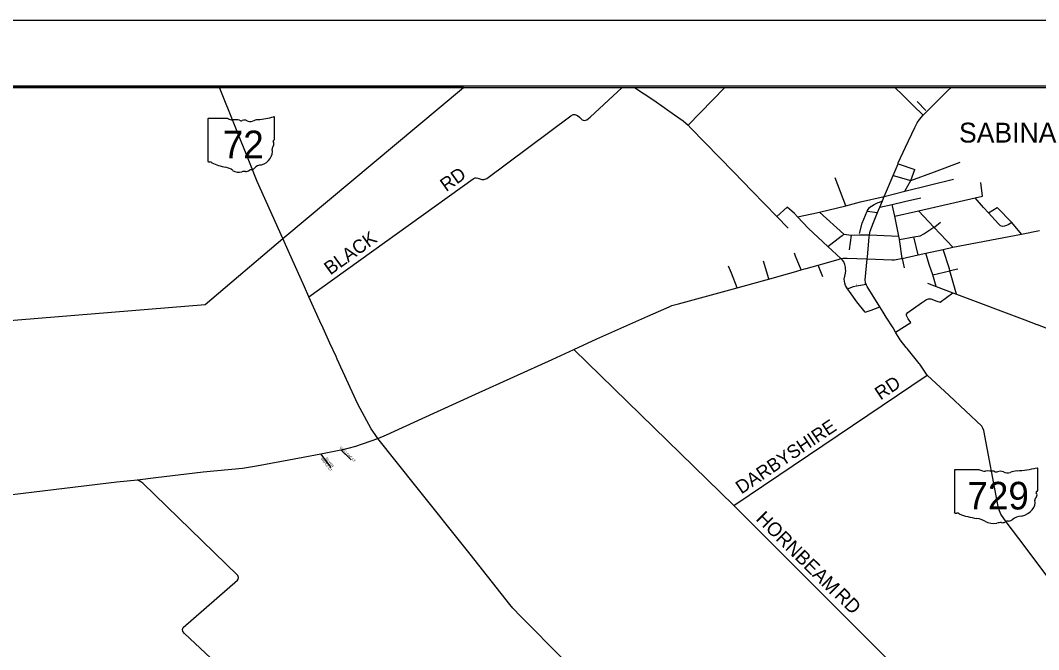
# Model space of a CAD drawing. Extents: x 0 to 784, y 0 to 440.
# Drawn here: x 111 to 266.5, y 343.9 to 440 of the extents above; entities that cross this region are included whole.
import ezdxf

# ---------------------------------------------------------------- set-up
doc = ezdxf.new("R2010")
doc.units = 0
for name, color, linetype in [('Default', 7, 'Continuous'), ('SH_Border', 7, 'Continuous'), ('SH_Cut_Line', 7, 'Continuous')]:
    doc.layers.add(name, color=color, linetype=linetype)

msp = doc.modelspace()

# ---------------------------------------------------------------- linework, layer by layer
at = {"layer": 'Default'}
for p, q in [((178.64, 429.76), (30.04, 429.76)), ((139.59, 424.91), (139.59, 418.5)), ((142.68, 425.02), (139.7, 425.02)), ((149.78, 421.83), (149.78, 425.18)), ((149.78, 421.83), (149.78, 421.83)), ((225.28, 400.54), (224.47, 403.23)), ((253.62, 371.3), (253.62, 364.89)), ((257.47, 371.41), (253.74, 371.41)), ((266.35, 368.22), (266.35, 371.57)), ((266.35, 368.22), (266.35, 368.22))]:
    msp.add_line(p, q, dxfattribs=at)
for points in [[(30.04, 417.42), (46.56, 400.57), (46.68, 400.45), (57.02, 389.91), (139.18, 396.63), (151.04, 406.68), (178.64, 429.76)], [(30.04, 429.76), (356.24, 429.76)], [(30.04, 429.76), (356.24, 429.76)], [(30.04, 429.76), (356.24, 429.76)], [(154.37, 399.31), (151.85, 404.86), (151.04, 406.68), (147.16, 415.39), (146.07, 418.12), (141.38, 429.76)], [(155.05, 397.8), (180.15, 415.83), (180.41, 415.96), (180.59, 415.99), (180.86, 415.92), (181.47, 415.71), (181.73, 415.7), (182.2, 415.87), (195.03, 425.41), (195.38, 425.64), (195.63, 425.65), (196.08, 425.49), (196.38, 425.24), (196.6, 424.97), (196.77, 424.81), (197.07, 424.74), (197.47, 424.81), (198.01, 425.2), (202.88, 429.76)], [(204.79, 429.76), (207.71, 427.84), (210.9, 425.56), (212.18, 424.68), (212.95, 423.99), (213.37, 423.53), (219.88, 416.89), (222.76, 413.93)], [(212.95, 423.99), (218.56, 429.76)], [(244.51, 429.76), (245.73, 428.57)], [(251.09, 427.76), (251.09, 427.76), (252.59, 429.24), (253.13, 429.76)], [(245.73, 428.57), (247.35, 427), (248.85, 425.54)], [(248.85, 425.54), (248.85, 425.54), (251.09, 427.76)], [(249.27, 426.26), (247.93, 427.62)], [(243.24, 413.92), (243.24, 413.92), (244.26, 416.34), (245.01, 418.12), (245.06, 418.24), (246.13, 420.64), (247.59, 423.64), (247.94, 424.35), (248.28, 424.86), (248.85, 425.54)], [(245.01, 418.12), (247.6, 417.25)], [(246.07, 413.93), (246.97, 415.56), (247.6, 417.25)], [(246.97, 415.56), (250.56, 416.89), (254.52, 418.34)], [(237.06, 411.7), (235.41, 415.98)], [(242.91, 413.12), (246.07, 413.93), (253.49, 415.74)], [(244.26, 416.34), (246.97, 415.56)], [(222.76, 413.93), (222.76, 413.92), (226.5, 410.07), (228.26, 408.27)], [(240.33, 403.92), (240.33, 403.92), (240.62, 406.89), (240.66, 407.19), (240.67, 407.28), (240.77, 407.82), (241.26, 409.17), (241.89, 410.68), (242.22, 411.47), (242.63, 412.44), (242.91, 413.12), (243.24, 413.92)], [(257.89, 413.17), (257.67, 415.23)], [(229.67, 410.01), (231.83, 410.48), (233, 410.72), (237.06, 411.7), (239.3, 412.29), (242.91, 413.12)], [(240.95, 411.66), (241.35, 411.9), (241.96, 412.18), (242.2, 412.27), (242.63, 412.44)], [(242.22, 411.47), (244.13, 411.91), (245.99, 412.34), (245.99, 412.34)], [(244.52, 410.1), (248.13, 410.93), (256.79, 412.92), (257.89, 413.17)], [(245.99, 412.34), (248.51, 412.93)], [(262.37, 409.13), (261.84, 408.81), (261.58, 408.7), (261.29, 408.6), (261.03, 408.55), (260.64, 408.62), (260.34, 408.93), (258.81, 410.64), (258.07, 411.46), (256.79, 412.92)], [(226.5, 410.07), (228.09, 411.47)], [(236.26, 403.64), (234.27, 405.49), (231.36, 408.25), (229.67, 410.01), (229.2, 410.5), (228.09, 411.47)], [(236.74, 407.39), (233, 410.72)], [(239.14, 407.49), (239.56, 409.03), (240.07, 410.29), (240.28, 410.86), (240.61, 411.38), (240.92, 411.64), (240.95, 411.66), (240.95, 411.66)], [(240.28, 410.86), (241.89, 410.68)], [(245.65, 403.67), (245.23, 406.55), (245.23, 406.58), (245.12, 407.08), (245.02, 407.58), (244.52, 410.1), (244.13, 411.91)], [(253.38, 405.36), (250.49, 408.42), (248.13, 410.93)], [(258.81, 410.64), (258.81, 410.64), (260.13, 411.46)], [(263.85, 407.39), (262.37, 409.13), (260.13, 411.46)], [(245.23, 406.55), (247.44, 406.94), (248.37, 407.09), (248.97, 407.44), (250.49, 408.42), (250.62, 408.51), (251.51, 409.2)], [(253.38, 405.36), (263.85, 407.39), (266.62, 407.92), (266.62, 407.92)], [(234.27, 405.49), (236.33, 407.04), (236.57, 407.23), (236.74, 407.39), (237.9, 407.23), (239.1, 407.25), (239.13, 407.25)], [(237.61, 404.98), (237.9, 407.23)], [(239.13, 407.25), (239.14, 407.25), (240.67, 407.28)], [(240.67, 407.28), (240.67, 407.28), (245.12, 407.08)], [(248.1, 404.2), (247.44, 406.94)], [(230.24, 401.9), (229.36, 404.03), (229.19, 404.48)], [(230.95, 402.1), (230.96, 402.11), (232.81, 402.64), (233.53, 402.84), (235.87, 403.52), (236.26, 403.64), (236.65, 403.72), (237.25, 403.71), (238.72, 403.66), (240.3, 403.6), (244.05, 403.45), (244.5, 403.46), (245.49, 403.64), (245.65, 403.67), (248.1, 404.2), (249.26, 404.46), (251.89, 405.03), (253.38, 405.36)], [(250.85, 399.39), (250.34, 401.15), (249.78, 402.76), (249.26, 404.46)], [(253.96, 398.22), (252.94, 401.79), (252.86, 402.06), (251.89, 405.03)], [(240.01, 395.45), (238.72, 397.06), (237.6, 398.62), (237.31, 399.01), (237, 399.54), (236.89, 399.89), (236.8, 400.49), (236.99, 401.39), (237.02, 401.83), (237.01, 402.01), (236.97, 402.31), (236.91, 402.74), (236.76, 403.14), (236.55, 403.39), (236.26, 403.64)], [(240.07, 399.91), (240.04, 399.99), (239.99, 400.42), (240.3, 403.6), (240.33, 403.92)], [(245.65, 403.67), (245.93, 402.24)], [(220.46, 399.19), (219.57, 401.4), (219.12, 402.49)], [(224.31, 400.25), (224.32, 400.25), (225.41, 400.55), (228.11, 401.29), (229.06, 401.56), (230.24, 401.9), (230.95, 402.1)], [(233.55, 400.87), (232.81, 402.64)], [(250.34, 401.15), (252.94, 401.79), (253, 401.8), (253, 401.8)], [(253, 401.8), (254.14, 402.08)], [(109.7, 367.64), (125.69, 369.54), (128.88, 369.87), (131.68, 370.22), (138.87, 371.09), (144.9, 371.67), (147.03, 372.02), (154.14, 373.35), (156.88, 373.86), (159.9, 374.42), (160.08, 374.46), (161.02, 374.69), (162.23, 375), (165.56, 376.17), (166.89, 376.71), (172.36, 379.21), (180.5, 382.96), (192.21, 388.23), (195.52, 389.76), (199.02, 391.4), (206.82, 394.86), (210.04, 396.28), (210.47, 396.46), (211.49, 396.72), (220.46, 399.19), (224.31, 400.25)], [(237.31, 399.01), (238.2, 399.37), (238.65, 399.5), (239.26, 399.6), (240.14, 399.72)], [(246.39, 389.92), (246.28, 390.05), (245.32, 391.23), (244.64, 392.39), (244.26, 393.05), (243.21, 394.71), (242.74, 395.44), (242.23, 396.26), (240.28, 399.38), (240.2, 399.58), (240.14, 399.72), (240.07, 399.91)], [(249.51, 399.9), (250.85, 399.39), (253.4, 398.43), (253.96, 398.22), (264.37, 394.31), (266.23, 393.59), (266.24, 393.59)], [(164.8, 377.29), (164.55, 377.64), (162.49, 381.42), (159.37, 388.29), (159.19, 388.7), (158.25, 390.75), (157.22, 393.03), (156.73, 394.1), (155.05, 397.8), (154.37, 399.31)], [(251.43, 397), (253.4, 398.43)], [(246.97, 393.86), (246.54, 394.42), (246.39, 394.75), (246.32, 394.97), (246.33, 395.16), (246.5, 395.4), (248.58, 396.86), (249.36, 397.38), (249.68, 397.49), (250.04, 397.51), (250.93, 397.15), (251.43, 397)], [(240.01, 395.45), (240.93, 395.79), (242.23, 396.26)], [(244.64, 392.39), (246.97, 393.86)], [(266.24, 393.59), (281.02, 387.86), (299.06, 380.98), (299.61, 380.85), (300.45, 380.74), (308.98, 379.61), (309.76, 379.47), (310.48, 379.21), (323.28, 374.64), (329.13, 372.44), (335.56, 369.94), (337.17, 369.28), (338.76, 368.39), (340.24, 367.53), (341.15, 366.72), (349.62, 359.12)], [(253.59, 332.34), (253.59, 332.34), (253.08, 332.85), (251.35, 334.57), (219.92, 365.94), (195.52, 389.76)], [(248.32, 387.52), (248.28, 387.58), (248.24, 387.64), (246.39, 389.92)], [(249.44, 385.84), (248.32, 387.52)], [(219.92, 365.94), (249.44, 385.84)], [(305.41, 312.35), (280.81, 339.02), (276.57, 343.66), (275.24, 345.07), (274.02, 346.43), (273.72, 346.74), (273.43, 347.14), (272.46, 348.48), (270.65, 351.32), (264.44, 359.64), (261.54, 363.43), (260.73, 364.63), (260.5, 365.11), (260.32, 365.8), (258.12, 377.41), (257.92, 377.84), (257.79, 378.04), (252.84, 382.75), (249.44, 385.84)], [(165.56, 376.17), (165.28, 376.64), (164.8, 377.29)], [(276.05, 250.6), (251.83, 278.94), (240.55, 292.26), (235.97, 297.77), (222.12, 314.36), (221.59, 314.93), (219.74, 316.8), (212.53, 323.9), (207.71, 328.65), (203.58, 332.82), (194.21, 342.12), (187.04, 349.36), (186.53, 349.9), (186.16, 350.28), (185.74, 350.86), (179.65, 358.52), (171.36, 368.89), (165.56, 376.17)], [(158.44, 371.76), (156.88, 373.86)], [(161.5, 372.9), (159.9, 374.42)], [(179.06, 306.25), (158.47, 325.4), (136.03, 346.4), (135.78, 346.71), (135.74, 347.01), (135.85, 347.34), (144.14, 354.57), (144.25, 354.72), (144.27, 354.94), (144.18, 355.26), (129.68, 369.35), (129.37, 369.54), (128.88, 369.87)]]:
    msp.add_lwpolyline(points, dxfattribs=at)
msp.add_lwpolyline([(31.33, 429.99), (465.77, 429.99), (465.77, 10.05), (31.33, 10.05)], close=True, dxfattribs=at)
for centre, major_axis, ratio, start_param, end_param in [((139.71, 424.92), (0.118, 0), 0.82844, 1.712693, 3.28349), ((143.39, 425.76), (1.14, 0), 0.82844, 4.042523, 4.731795), ((143.77, 421.42), (4.11, 0), 0.82844, 1.404758, 1.657858), ((144.7, 424.95), (0.33, 0), 0.82844, 3.836095, 5.185415), ((145.19, 424.21), (0.686, 0), 0.82844, 0.950623, 2.079405), ((146.07, 425.23), (0.826, 0), 0.82844, 4.081561, 5.145723), ((147.53, 423.06), (2.17, 0), 0.82844, 1.699011, 2.107814), ((146.15, 433.75), (10.8, 0), 0.82844, 4.814394, 5.042369), ((149.67, 425.19), (0.113, 0), 0.82844, 6.141152, 7.989035), ((149.75, 421.58), (0.175, 0), 0.82844, 1.883978, 3.671073), ((148.64, 421.16), (1.05, 0), 0.82844, 5.934695, 6.695948), ((149.66, 421.81), (0.121, 0), 0.82844, 5.05454, 6.418171), ((146.76, 420), (2.7, 0), 0.82844, 5.101752, 6.440018), ((150.19, 420.42), (0.766, 0), 0.82844, 2.387724, 3.262537), ((139.71, 418.49), (0.119, 0), 0.82844, 3.00124, 4.508301), ((139.73, 419.14), (0.908, 0), 0.82844, 4.665946, 4.897461), ((139.92, 418.13), (0.328, 0), 0.82844, 0.519207, 1.627899), ((144.05, 423.89), (7.8, 0), 0.82844, 4.195997, 4.488961), ((141.73, 415.63), (2.44, 0), 0.82844, 0.823519, 1.323587), ((144.37, 418.1), (1.55, 0), 0.82844, 4.026481, 4.996735), ((145.26, 415.89), (1.27, 0), 0.82844, 1.495662, 1.94098), ((145.37, 417.62), (0.825, 0), 0.82844, 4.691044, 5.507374), ((146.12, 417), (0.232, 0), 0.82844, 1.147584, 2.315152), ((146.02, 417.88), (0.873, 0), 0.82844, 4.937069, 5.64225), ((147.9, 416.7), (1.48, 0), 0.82844, 1.647645, 2.488434), ((253.76, 371.31), (0.147, 0), 0.662752, 1.712693, 3.28349), ((258.36, 372.15), (1.43, 0), 0.662752, 4.042523, 4.731795), ((258.83, 367.81), (5.14, 0), 0.662752, 1.404758, 1.657858), ((260, 371.34), (0.413, 0), 0.662752, 3.836095, 5.185415), ((260.6, 370.6), (0.858, 0), 0.662752, 0.950623, 2.079405), ((261.71, 371.62), (1.03, 0), 0.662752, 4.081561, 5.145723), ((263.53, 369.45), (2.72, 0), 0.662752, 1.699011, 2.107814), ((261.81, 380.14), (13.5, 0), 0.662752, 4.814394, 5.042369), ((266.21, 371.58), (0.142, 0), 0.662752, 6.141152, 7.989035), ((266.86, 366.81), (0.958, 0), 0.662752, 2.387724, 3.262537), ((266.32, 367.97), (0.219, 0), 0.662752, 1.883978, 3.671073), ((264.92, 367.55), (1.32, 0), 0.662752, 5.934695, 6.695948), ((266.2, 368.2), (0.152, 0), 0.662752, 5.05454, 6.418171), ((262.57, 366.39), (3.38, 0), 0.662752, 5.101752, 6.440018), ((253.76, 364.88), (0.149, 0), 0.662752, 3.00124, 4.508301), ((253.79, 365.53), (1.14, 0), 0.662752, 4.665946, 4.897461), ((254.02, 364.52), (0.409, 0), 0.662752, 0.519207, 1.627899), ((259.19, 370.28), (9.75, 0), 0.662752, 4.195997, 4.488961), ((256.28, 362.02), (3.05, 0), 0.662752, 0.823519, 1.323587), ((263.99, 363.09), (1.85, 0), 0.662752, 1.647645, 2.488434), ((259.58, 364.49), (1.94, 0), 0.662752, 4.026481, 4.996735), ((260.7, 362.28), (1.59, 0), 0.662752, 1.495662, 1.94098), ((260.84, 364.01), (1.03, 0), 0.662752, 4.691044, 5.507374), ((261.77, 363.39), (0.29, 0), 0.662752, 1.147584, 2.315152), ((261.65, 364.27), (1.09, 0), 0.662752, 4.937069, 5.64225)]:
    msp.add_ellipse(centre, major_axis=major_axis, ratio=ratio, start_param=start_param, end_param=end_param, dxfattribs=at)
at = {"layer": 'SH_Border'}
msp.add_lwpolyline([(30, 430), (670, 430), (670, 10), (30, 10)], close=True, dxfattribs=at)
at = {"layer": 'SH_Cut_Line'}
msp.add_lwpolyline([(0, 0), (680, 0), (680, 440), (0, 440)], close=True, dxfattribs=at)

# ---------------------------------------------------------------- texts
at = {"layer": 'Default'}
for s, p in [('72', (141.87, 418.95)), ('729', (255.59, 365.34))]:
    msp.add_text(s, height=4.219, dxfattribs=at).set_placement(p)
for s, height, rotation, p in [('SABINA', 3.031, 0, (254.33, 421.35)), ('RD', 2.055, 35.5809, (176.01, 413.77)), ('BLACK', 2.056, 35.7359, (158.3, 401.05)), ('I', 0.309, 10.9417, (238.63, 399.56)), ('T', 0.321, 20.5473, (241.98, 396.23)), ('RD', 2.042, 33.8986, (242.34, 381.97)), ('DARBYSHIRE', 2.042, 33.9794, (221.09, 367.62)), ('OAK LEAF CT', 0.3521, 316.323, (159.7, 374.75)), ('MAPLE CT', 0.36, 307.3207, (156.83, 373.08)), ('SILVER', 0.36, 306.7659, (157.52, 373.17)), ('HORNBEAM', 2.12, 315.0909, (223.2, 363.79)), ('RD', 2.12, 315.1058, (235.17, 352.06))]:
    msp.add_text(s, height=height, rotation=rotation, dxfattribs=at).set_placement(p)

doc.saveas('drawing.dxf')
